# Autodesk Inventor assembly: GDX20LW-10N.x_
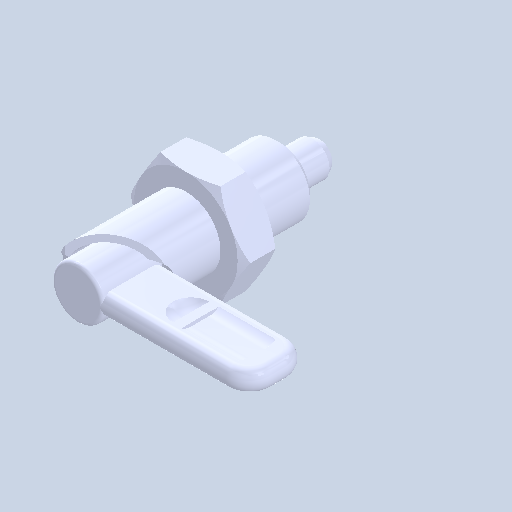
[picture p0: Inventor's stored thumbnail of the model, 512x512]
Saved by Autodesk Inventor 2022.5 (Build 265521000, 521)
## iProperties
Created: 2024-06
Part Number: GDX20LW-10N.x_
Document SubType Name: Assembly
Designer: ImaoCorp
Author: ImaoCorp
Sending System: SOLIDWORKS 2022-2022290
MC: AMD64
MC_MODEL: Intel64 Family 6 Model 60 Stepping 3, GenuineIntel
OS: Windows_NT
FRU: Parasolid Version 33.1, build 260,  4-25-2022
FORMAT: text
GUISE: transmit
KEY: FILEGDX20LW-10N.x_t
DATE: Wed Jun 12 09:32:58 2024
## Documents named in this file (4)
- Y:\5.更新分\2024年対応\xxxx_GDX\データ_imao品番\gdx20lw-10n\GDX20LW-10N.x_.iam
- Y:\5.更新分\2024年対応\xxxx_GDX\データ_imao品番\gdx20lw-10n\GDX20LW-10N_01.ipt
- Y:\5.更新分\2024年対応\xxxx_GDX\データ_imao品番\gdx20lw-10n\GDX20LW-10N_02.ipt
- Y:\5.更新分\2024年対応\xxxx_GDX\データ_imao品番\gdx20lw-10n\GDX20LW-10N_03.ipt
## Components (3 placed, 3 different names)
1. GDX20LW-10N_01
2. GDX20LW-10N_02
3. GDX20LW-10N_03
